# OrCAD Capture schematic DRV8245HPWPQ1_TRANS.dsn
size Custom; title: DRV8245-Q1 Automotive H-Bridge Driver with; rev: 1.0; note: Datasheet: SLVSFJ1A      EVM: NA; note: Synchronous Step Down Converter
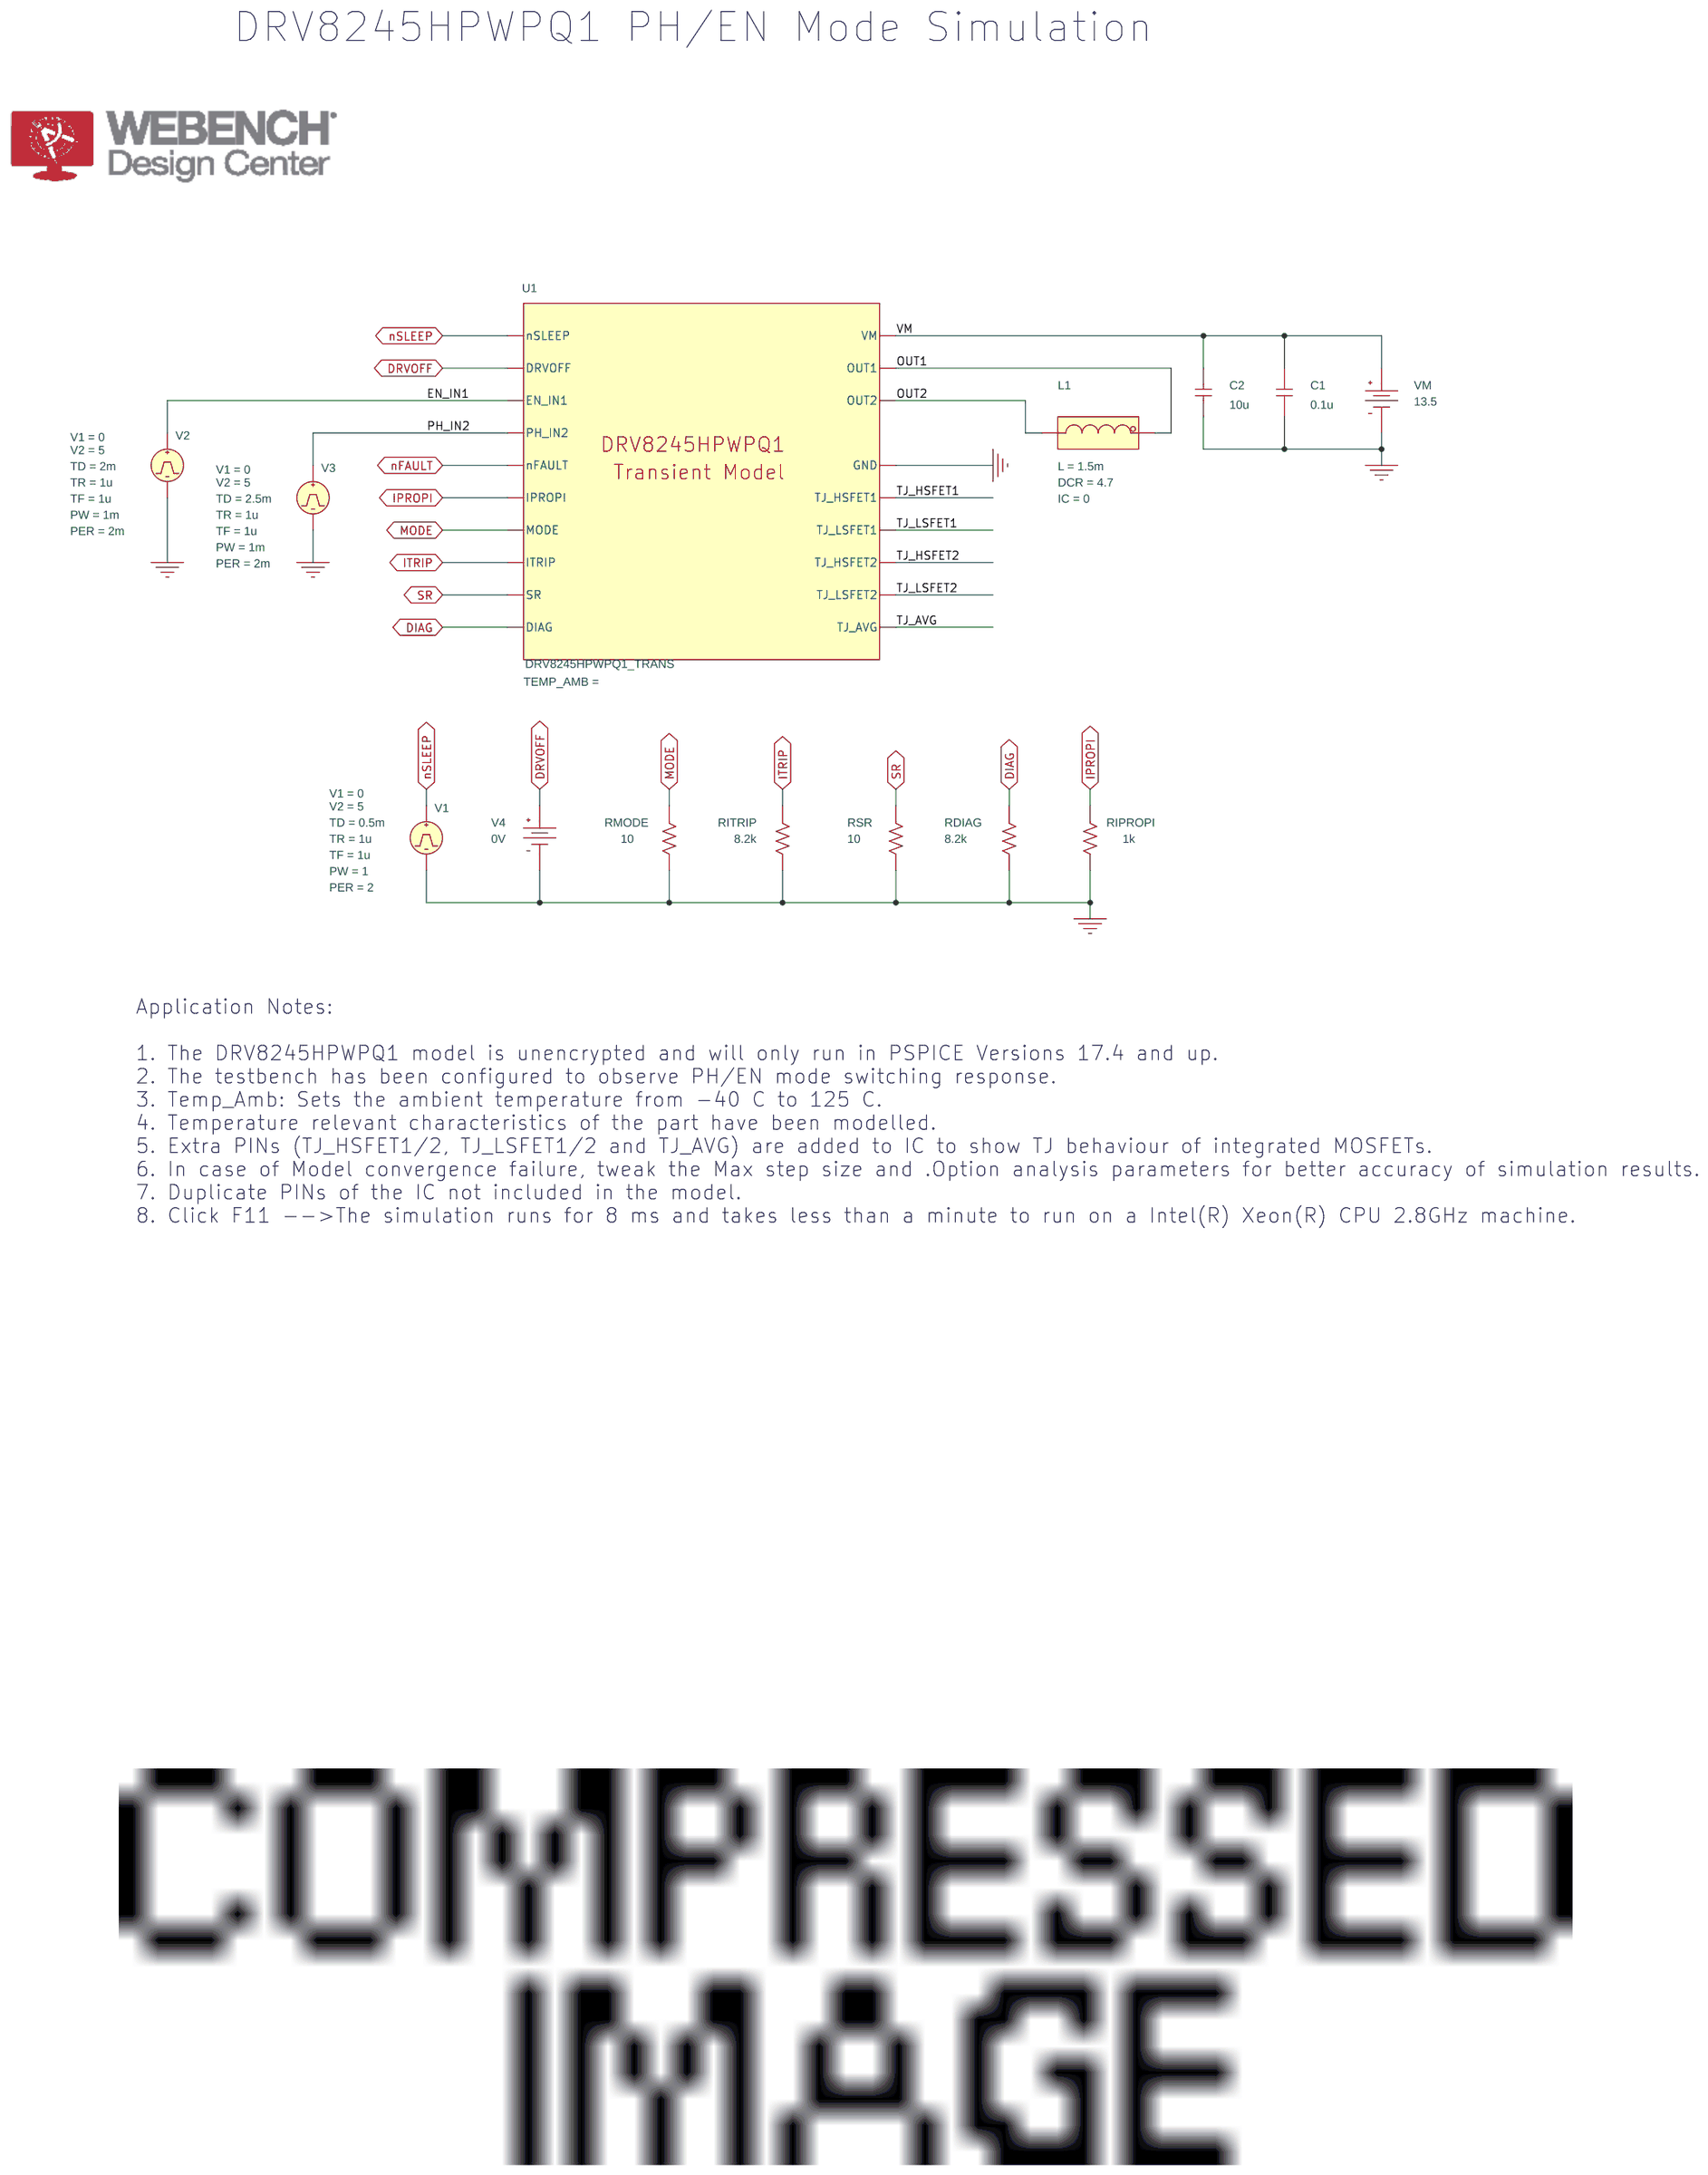
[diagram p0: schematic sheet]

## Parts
C1  0.1u  [RAD/CK05]
C2  10u  [RAD/CK05]
L1  LDCR
RDIAG  8.2k  [AXRC05]
RIPROPI  1k  [AXRC05]
RITRIP  8.2k  [AXRC05]
RMODE  10  [AXRC05]
RSR  10  [AXRC05]
U1  DRV8245HPWPQ1_TRANS
V1  VPULSE
V2  VPULSE
V3  VPULSE
V4  VDC
VM  VDC

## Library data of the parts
C1 C2 = C
L1 = LDCR: DCR: 4.7; IC: 0; L: 1.5m; PSpiceTemplate: X^@REFDES %IN %OUT @MODEL PARAMS:  ?L|L=@L||L=1u|  ?DCR|DCR=@DCR||DCR=0.01| ?IC|IC=@IC||IC=0|
RDIAG RIPROPI RITRIP RMODE RSR = R
U1 = DRV8245HPWPQ1_TRANS
V1 = VPULSE: PER: 2; PW: 1; TD: 0.5m; TF: 1u; TR: 1u; V1: 0; V2: 5
V2 = VPULSE: PER: 2m; PW: 1m; TD: 2m; TF: 1u; TR: 1u; V1: 0; V2: 5
V3 = VPULSE: PER: 2m; PW: 1m; TD: 2.5m; TF: 1u; TR: 1u; V1: 0; V2: 5
V4 = VDC: DC: 0V
VM = VDC: DC: 13.5

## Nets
0: C1.2 C2.2 RDIAG.2 RIPROPI.2 RITRIP.2 RMODE.2 RSR.2 U1.GND V1.2(-) V2.2(-) V3.2(-) V4.1(-) VM.1(-)
DIAG: RDIAG.1 U1.DIAG
DRVOFF: U1.DRVOFF V4.0(+)
EN_IN1: U1.EN_IN1 V2.1(+)
IPROPI: RIPROPI.1 U1.IPROPI
ITRIP: RITRIP.1 U1.ITRIP
MODE: RMODE.1 U1.MODE
nFAULT: U1.nFAULT
nSLEEP: U1.nSLEEP V1.1(+)
OUT1: L1.1(IN) U1.OUT1
OUT2: L1.3(OUT) U1.OUT2
PH_IN2: U1.PH_IN2 V3.1(+)
SR: RSR.1 U1.SR
TJ_AVG: U1.TJ_AVG
TJ_HSFET1: U1.TJ_HSFET1
TJ_HSFET2: U1.TJ_HSFET2
TJ_LSFET1: U1.TJ_LSFET1
TJ_LSFET2: U1.TJ_LSFET2
VM: C1.1 C2.1 U1.VM VM.0(+)

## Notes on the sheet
- DRV8245HPWPQ1 PH/EN Mode Simulation
- Application Notes:
  1. The DRV8245HPWPQ1 model is unencrypted and will only run in PSPICE Versions 17.4 and up.
  2. The testbench has been configured to observe PH/EN mode switching response.
  3. Temp_Amb: Sets the ambient temperature from -40 C to 125 C.
  4. Temperature relevant characteristics of the part have been modelled.
  5. Extra PINs (TJ_HSFET1/2, TJ_LSFET1/2 and TJ_AVG) are added to IC to show TJ behaviour of integrated MOSFETs.
  6. In case of Model convergence failure, tweak the Max step size and .Option analysis parameters for better accuracy of simulation results.
  7. Duplicate PINs of the IC not included in the model.
  8. Click F11 -->The simulation runs for 8 ms and takes less than a minute to run on a Intel(R) Xeon(R) CPU 2.8GHz machine.
